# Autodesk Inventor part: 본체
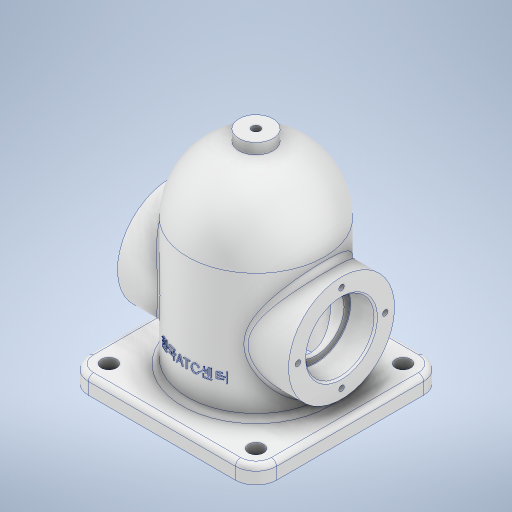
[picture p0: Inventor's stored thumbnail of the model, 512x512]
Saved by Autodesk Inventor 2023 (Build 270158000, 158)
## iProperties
Created: 2025-04
Part Number: 본체
Material: 알루미늄 6061
Document SubType Name: Modeling
Designer: user
Mass: 865.865 g
Surface Area: 800.948 cm^2
Volume: 320.691 cm^3
Density: 2.7 g/cm^3
Appearance: 알루미늄 - 평지
Author: user
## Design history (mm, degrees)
sketch "스케치5"
  geometry: L1 (-55, 55)-(55, 55); L2 (55, 55)-(55, -55); L3 (55, -55)-(-55, -55); L4 (-55, -55)-(-55, 55); L5 (-55, 55)-(55, -55); L6 (55, 55)-(-55, -55); 1 further point
  constraints: 12 end point, 2 midpoint, 2 parallel, 1 horizontal, 1 perpendicular
  dimensions: "d12" = 110 distance of L1.end L2.end; "d13" = 110 distance of L2.end L3.end
extrude "돌출4" new body sketch "스케치5" distance "d14" = 10; taper "d15" = 0 deg
sketch "스케치6"
  geometry: C1 r 40 at (0, 0); 1 further point
  constraints: 1 centre point, 1 coincident
  dimensions: "d16" = 80 diameter of C1
extrude "돌출5" join sketch "스케치6" distance "d17" = 74; taper "d18" = 0 deg
sketch "스케치7"
  geometry: L1 (84, -40)-(84, 40) reference; L2 (-25.895, 0)-(155.372, 0) reference; L3 (84, 40)-(84, 0); L4 (124, 0)-(84, 0); A1 r 40 centre (84, 0) between (124, 0) and (84, 40); 1 further point
  constraints: 4 end point, 2 perpendicular, 2 point on circle, 1 centre point, 1 midpoint, 1 point on line
revolve "회전2" sketch "스케치7" stored, may be unused: angle "d19" = 90 deg
node "작업 평면2"
sketch "스케치8"
  geometry: C1 r 10 at (0, 0); 1 further point
  constraints: 1 centre point, 1 coincident
  dimensions: "d21" = 20 diameter of C1
extrude "돌출6" join sketch "스케치8" stored distance "d22" = 74; taper "d23" = 0 deg
sketch "스케치10"
  geometry: L1 (0, -55)-(0, 55) reference; L2 (0, -55)-(10, -55) reference; C1 r 31 at (48, 0); 1 further point
  constraints: 1 centre point
  dimensions: "d24" = 48 distance from line of L1 C1.centre; "d25" = 55 distance from line of L2 C1.centre; "d26" = 62 diameter of C1
extrude "돌출7" join sketch "스케치10" stored distance "d27" = 100; taper "d28" = 0 deg
sketch "스케치11"
  geometry: C1 r 31 at (0, 0) reference; C2 r 20 at (0, 0); 2 further points
  constraints: 2 coincident, 1 centre point
  dimensions: "d29" = 40 diameter of C2
extrude "돌출8" cut sketch "스케치11" distance "d30" = 15; taper "d31" = 0 deg
sketch "스케치12"
  geometry: C1 r 16.5 at (0, 0); 1 further point
  constraints: 1 centre point
  dimensions: "d32" = 33 diameter of C1
extrude "돌출9" cut sketch "스케치12" stored distance "d33" = 15; taper "d34" = 0 deg
sketch "스케치13" dims "d35" = 51
  geometry: C1 r 20 at (0, 0) reference; 3 further points
  constraints: 1 coincident, 1 vertical alignment, 2 other
hole "구멍1" sketch "스케치13" at (0, 25.5) diameter "d36" = 3.242; stored, may be unused: countersink angle "d40" = 82 deg, drill point angle "d42" = 118 deg; dims "d37" = 8, "d38" = 3.023, "d39" = 2, "d41" = 10
sketch "스케치14"
  geometry: L1 (0, 0)-(32, 0); L2 (-55, 0)-(55, 0) reference; L3 (32, 0)-(32, 84); L4 (32, 84)-(0, 84); L5 (0, 84)-(0, 0); L6 (0, -25.8)-(0, 154.8) reference; L7 (0, 116)-(0, 84); L8 (40, 84)-(-40, 84) reference; A1 r 32 centre (0, 84) between (32, 84) and (0, 116)
  constraints: 10 end point, 3 perpendicular, 2 point on circle, 2 point on line, 1 centre point, 1 coincident, 1 vertical
  dimensions: "d46" = 32 distance of L1.start L1.end; "d47" = 84 distance of L1.end L3.end
revolve "회전3" sketch "스케치14" stored, may be unused: angle "d48" = 90 deg
sketch "스케치15"
  geometry: L1 (43, -43)-(-43, -43); L2 (-43, -43)-(-43, 43); L3 (-43, 43)-(43, 43); L4 (43, 43)-(43, -43); L5 (43, -43)-(-43, 43); L6 (-43, -43)-(43, 43); C1 r 32 at (0, 0) reference; C2 r 4.5 at (-43, -43); C3 r 4.5 at (-43, 43); C4 r 4.5 at (43, 43); C5 r 4.5 at (43, -43); 1 further point
  constraints: 12 end point, 4 centre point, 4 coincident, 2 midpoint, 2 parallel, 1 horizontal, 1 perpendicular
  dimensions: "d49" = 86 distance of L1.end L2.end; "d50" = 86 distance of L2.end L3.end; "d51" = 9 diameter of C5; "d52" = 9 diameter of C2; "d53" = 9 diameter of C3; "d54" = 9 diameter of C4
extrude "돌출10" cut sketch "스케치15" stored distance "d55" = 10; taper "d56" = 0 deg
node "작업 평면3"
sketch "스케치16"
  geometry: L1 (-55, 0)-(55, 0) reference; L2 (0, -25.8)-(0, 154.8) reference; 2 further points
  constraints: 1 point on line, 1 other
  dimensions: "d58" = 30 distance from line of L1 point (0, 30)
feature "엠보싱1" sketch "스케치16" dims "d12" = 110, "d13" = 110, "d21" = 20, "d59" = 0.5, "d60" = 0
fillet "모깎기1" dims "d61" = 12
fillet "모깎기2" dims "d62" = 3
chamfer "모따기1" distance "d63" = 1; stored, may be unused: second distance "d64" = 2, angle "d65" = 45 deg
fillet "모깎기3" dims "d66" = 0.3
sketch "스케치17"
  geometry: 1 further point
hole "구멍2" sketch "스케치17" at (0, 0) diameter "d67" = 4.917; stored, may be unused: countersink angle "d71" = 90 deg, drill point angle "d73" = 0 deg; dims "d68" = 12, "d69" = 4, "d70" = 2, "d72" = 8
node "솔리드2"
mirror "미러1"
pattern_circular "원형 패턴1" dims angle "d44" = 360 deg
mirror "미러2"
feature "A9D066F2-1C7D-4E18-AEED-F7BC21143FA4" dims "d36" = 3.242, "d37" = 8, "d38" = 3.023, "d39" = 2, "d40" = 82 deg, "d41" = 10, "d42" = 118 deg
other parameters: "d20" = 129, "d57" = 193
